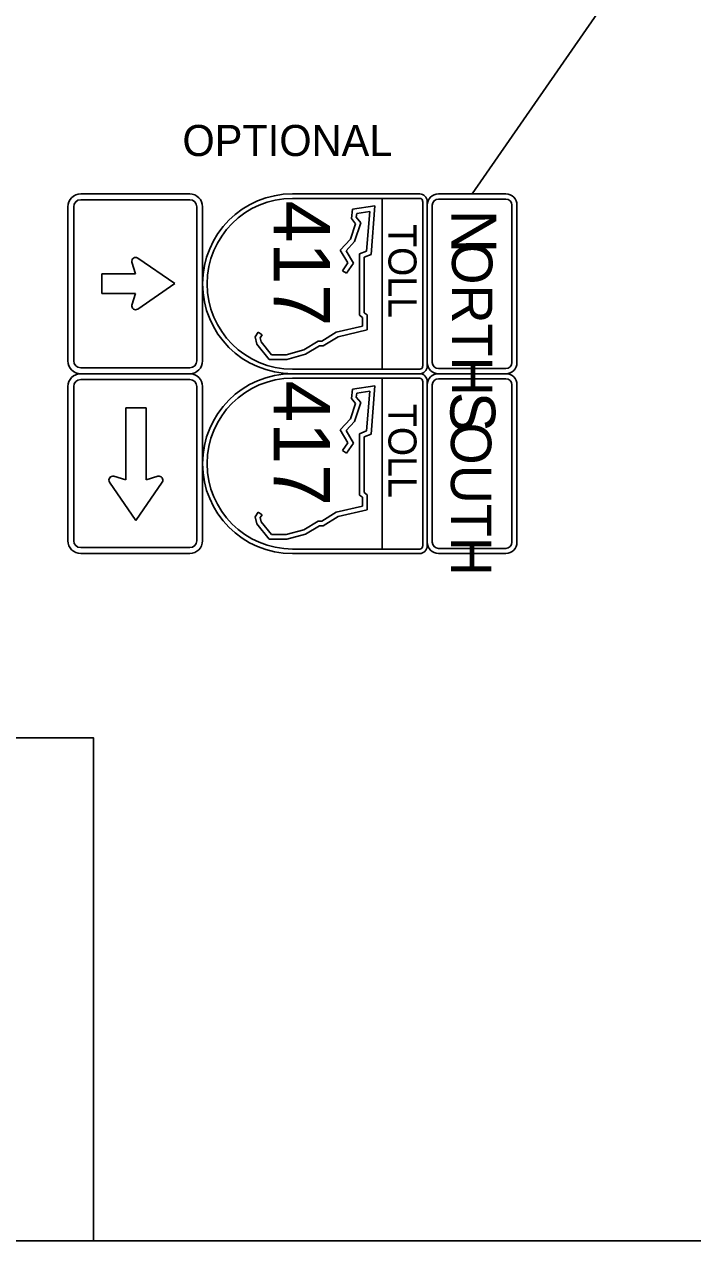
# Model space of a CAD drawing. Extents: x -830008.4 to -829992.7, y 1290284.1 to 1290294.4.
# Drawn here: x -830003.674 to -830002.168, y 1290285.328 to 1290288.067 of the extents above; entities that cross this region are included whole.
import ezdxf

# ---------------------------------------------------------------- set-up
doc = ezdxf.new("R2010")
doc.units = 0
for name, color, linetype in [('1', 7, 'Continuous'), ('SheetBorder_dp', 7, 'Continuous'), ('SheetLines_dp', 7, 'Continuous')]:
    doc.layers.add(name, color=color, linetype=linetype)

msp = doc.modelspace()

# ---------------------------------------------------------------- linework, layer by layer
at = {"layer": '1'}
msp.add_line((-830001.6762, 1290289.1116), (-830002.665, 1290287.6856), dxfattribs=at)
msp.add_lwpolyline([(-830007.4742, 1290285.328), (-830003.5187, 1290285.328), (-830003.5187, 1290286.4608), (-830007.4742, 1290286.4608)], close=True, dxfattribs=at)
at = {"layer": 'SheetBorder_dp'}
for p, q in [((-830002.9344, 1290287.6508), (-830002.8844, 1290287.6586)), ((-830002.8844, 1290287.6586), (-830002.8928, 1290287.5492)), ((-830002.937, 1290287.6298), (-830002.9344, 1290287.6508)), ((-830002.928, 1290287.6184), (-830002.937, 1290287.6298)), ((-830002.9249, 1290287.6416), (-830002.926, 1290287.6329)), ((-830002.926, 1290287.6329), (-830002.9162, 1290287.6205)), ((-830002.8959, 1290287.6461), (-830002.9249, 1290287.6416)), ((-830002.9028, 1290287.5566), (-830002.8959, 1290287.6461)), ((-830002.9393, 1290287.5838), (-830002.928, 1290287.6184)), ((-830002.9162, 1290287.6205), (-830002.93, 1290287.5783)), ((-830002.9622, 1290287.559), (-830002.9393, 1290287.5838)), ((-830002.93, 1290287.5783), (-830002.9491, 1290287.5576)), ((-830002.9451, 1290287.5299), (-830002.9622, 1290287.559)), ((-830002.9491, 1290287.5576), (-830002.9326, 1290287.5295)), ((-830002.9191, 1290287.5503), (-830002.9028, 1290287.5566)), ((-830002.9191, 1290287.4121), (-830002.9191, 1290287.5503)), ((-830002.8928, 1290287.5492), (-830002.9086, 1290287.5431)), ((-830003.4317, 1290287.5317), (-830003.4239, 1290287.5056)), ((-830003.335, 1290287.4835), (-830003.4188, 1290287.5411)), ((-830002.9568, 1290287.5126), (-830002.9451, 1290287.5299)), ((-830002.9326, 1290287.5295), (-830002.9481, 1290287.5067)), ((-830002.9086, 1290287.5431), (-830002.9086, 1290287.4177)), ((-830003.4239, 1290287.5056), (-830003.4995, 1290287.5056)), ((-830003.4995, 1290287.5056), (-830003.4995, 1290287.4613)), ((-830002.9481, 1290287.5067), (-830002.9568, 1290287.5126)), ((-830003.4188, 1290287.4259), (-830003.335, 1290287.4835)), ((-830003.4995, 1290287.4613), (-830003.4239, 1290287.4613)), ((-830003.4239, 1290287.4613), (-830003.4317, 1290287.4353)), ((-830002.9121, 1290287.4073), (-830002.9191, 1290287.4121)), ((-830002.9121, 1290287.3876), (-830002.9121, 1290287.4073)), ((-830002.9086, 1290287.4177), (-830002.9016, 1290287.4129)), ((-830002.9016, 1290287.4129), (-830002.9016, 1290287.3792)), ((-830002.9714, 1290287.3738), (-830002.9121, 1290287.3876)), ((-830003.1544, 1290287.3636), (-830003.1472, 1290287.374)), ((-830003.1505, 1290287.3472), (-830003.1544, 1290287.3636)), ((-830003.1472, 1290287.374), (-830003.1385, 1290287.368)), ((-830003.1385, 1290287.368), (-830003.143, 1290287.3615)), ((-830003.143, 1290287.3615), (-830003.1408, 1290287.352)), ((-830003.0444, 1290287.3341), (-830003.0121, 1290287.3536)), ((-830003.0121, 1290287.3536), (-830003.0038, 1290287.3536)), ((-830003.0038, 1290287.3536), (-830002.9714, 1290287.3738)), ((-830002.9673, 1290287.3639), (-830003.0007, 1290287.3431)), ((-830002.9016, 1290287.3792), (-830002.9673, 1290287.3639)), ((-830003.1222, 1290287.3127), (-830003.1505, 1290287.3472)), ((-830003.1408, 1290287.352), (-830003.1172, 1290287.3232)), ((-830003.084, 1290287.3232), (-830003.0444, 1290287.3341)), ((-830003.0092, 1290287.3431), (-830003.0402, 1290287.3243)), ((-830003.0007, 1290287.3431), (-830003.0092, 1290287.3431)), ((-830003.0826, 1290287.3127), (-830003.1222, 1290287.3127)), ((-830003.1172, 1290287.3232), (-830003.084, 1290287.3232)), ((-830003.0402, 1290287.3243), (-830003.0826, 1290287.3127)), ((-830002.937, 1290287.2248), (-830002.9344, 1290287.2458)), ((-830002.9344, 1290287.2458), (-830002.8844, 1290287.2536)), ((-830002.8844, 1290287.2536), (-830002.8928, 1290287.1442)), ((-830002.928, 1290287.2134), (-830002.937, 1290287.2248)), ((-830002.9162, 1290287.2155), (-830002.93, 1290287.1733)), ((-830002.9249, 1290287.2366), (-830002.926, 1290287.2279)), ((-830002.926, 1290287.2279), (-830002.9162, 1290287.2155)), ((-830002.8959, 1290287.2411), (-830002.9249, 1290287.2366)), ((-830002.9028, 1290287.1516), (-830002.8959, 1290287.2411)), ((-830003.4456, 1290287.0415), (-830003.4456, 1290287.2039)), ((-830003.4456, 1290287.2039), (-830003.4001, 1290287.2039)), ((-830003.4001, 1290287.2039), (-830003.4001, 1290287.0415)), ((-830002.9393, 1290287.1788), (-830002.928, 1290287.2134)), ((-830002.9622, 1290287.154), (-830002.9393, 1290287.1788)), ((-830002.93, 1290287.1733), (-830002.9491, 1290287.1526)), ((-830002.9451, 1290287.1249), (-830002.9622, 1290287.154)), ((-830002.9491, 1290287.1526), (-830002.9326, 1290287.1245)), ((-830002.9191, 1290287.1453), (-830002.9028, 1290287.1516)), ((-830002.9191, 1290287.0071), (-830002.9191, 1290287.1453)), ((-830002.8928, 1290287.1442), (-830002.9086, 1290287.1381)), ((-830002.9086, 1290287.1381), (-830002.9086, 1290287.0127)), ((-830002.9568, 1290287.1076), (-830002.9451, 1290287.1249)), ((-830002.9481, 1290287.1017), (-830002.9568, 1290287.1076)), ((-830002.9326, 1290287.1245), (-830002.9481, 1290287.1017)), ((-830003.4228, 1290286.95), (-830003.4821, 1290287.0362)), ((-830003.4724, 1290287.0495), (-830003.4456, 1290287.0415)), ((-830003.3636, 1290287.0362), (-830003.4228, 1290286.95)), ((-830003.4001, 1290287.0415), (-830003.3732, 1290287.0495)), ((-830002.9121, 1290287.0023), (-830002.9191, 1290287.0071)), ((-830002.9121, 1290286.9826), (-830002.9121, 1290287.0023)), ((-830002.9086, 1290287.0127), (-830002.9016, 1290287.0079)), ((-830002.9016, 1290287.0079), (-830002.9016, 1290286.9742)), ((-830003.1544, 1290286.9586), (-830003.1472, 1290286.969)), ((-830003.1472, 1290286.969), (-830003.1385, 1290286.963)), ((-830003.0038, 1290286.9486), (-830002.9714, 1290286.9688)), ((-830002.9714, 1290286.9688), (-830002.9121, 1290286.9826)), ((-830002.9016, 1290286.9742), (-830002.9673, 1290286.9589)), ((-830003.1505, 1290286.9422), (-830003.1544, 1290286.9586)), ((-830003.1222, 1290286.9077), (-830003.1505, 1290286.9422)), ((-830003.1385, 1290286.963), (-830003.143, 1290286.9565)), ((-830003.143, 1290286.9565), (-830003.1408, 1290286.947)), ((-830003.1408, 1290286.947), (-830003.1172, 1290286.9182)), ((-830003.0444, 1290286.9291), (-830003.0121, 1290286.9486)), ((-830003.0121, 1290286.9486), (-830003.0038, 1290286.9486)), ((-830002.9673, 1290286.9589), (-830003.0007, 1290286.9381)), ((-830003.1172, 1290286.9182), (-830003.084, 1290286.9182)), ((-830003.084, 1290286.9182), (-830003.0444, 1290286.9291)), ((-830003.0402, 1290286.9193), (-830003.0826, 1290286.9077)), ((-830003.0092, 1290286.9381), (-830003.0402, 1290286.9193)), ((-830003.0007, 1290286.9381), (-830003.0092, 1290286.9381)), ((-830003.0826, 1290286.9077), (-830003.1222, 1290286.9077))]:
    msp.add_line(p, q, dxfattribs=at)
for points in [[(-830003.5473, 1290287.6856), (-830003.3015, 1290287.6856)], [(-830003.07, 1290287.6856), (-830002.7832, 1290287.6856)], [(-830002.741, 1290287.6856), (-830002.5891, 1290287.6856)], [(-830003.5763, 1290287.3095), (-830003.5763, 1290287.6566)], [(-830003.563, 1290287.3095), (-830003.563, 1290287.6566)], [(-830003.5473, 1290287.6723), (-830003.3014, 1290287.6723)], [(-830003.2858, 1290287.6566), (-830003.2858, 1290287.3095)], [(-830003.2725, 1290287.6566), (-830003.2725, 1290287.3095)], [(-830003.07, 1290287.6754), (-830002.7832, 1290287.6754)], [(-830002.8675, 1290287.6754), (-830002.8675, 1290287.2907)], [(-830002.7764, 1290287.6687), (-830002.7764, 1290287.2974)], [(-830002.7663, 1290287.6687), (-830002.7663, 1290287.2974)], [(-830002.7663, 1290287.3059), (-830002.7663, 1290287.6603)], [(-830002.7547, 1290287.3059), (-830002.7547, 1290287.6603)], [(-830002.741, 1290287.674), (-830002.5891, 1290287.674)], [(-830002.5754, 1290287.6603), (-830002.5754, 1290287.3059)], [(-830002.5638, 1290287.6603), (-830002.5638, 1290287.3059)], [(-830003.3014, 1290287.2938), (-830003.5473, 1290287.2938)], [(-830003.3015, 1290287.2806), (-830003.5473, 1290287.2806)], [(-830003.3015, 1290287.2806), (-830003.5473, 1290287.2806)], [(-830002.7832, 1290287.2907), (-830003.07, 1290287.2907)], [(-830002.7832, 1290287.2806), (-830003.07, 1290287.2806)], [(-830003.07, 1290287.2806), (-830002.7832, 1290287.2806)], [(-830003.07, 1290287.2704), (-830002.7832, 1290287.2704)], [(-830002.8675, 1290287.2704), (-830002.8675, 1290286.8857)], [(-830002.5891, 1290287.2922), (-830002.741, 1290287.2922)], [(-830002.741, 1290287.2806), (-830002.5891, 1290287.2806)], [(-830002.5891, 1290287.2806), (-830002.741, 1290287.2806)], [(-830003.5763, 1290287.2516), (-830003.5763, 1290286.9045)], [(-830003.563, 1290287.2516), (-830003.563, 1290286.9045)], [(-830003.3014, 1290287.2673), (-830003.5473, 1290287.2673)], [(-830003.2858, 1290286.9045), (-830003.2858, 1290287.2516)], [(-830003.2725, 1290286.9045), (-830003.2725, 1290287.2516)], [(-830002.7764, 1290287.2637), (-830002.7764, 1290286.8924)], [(-830002.7663, 1290287.2637), (-830002.7663, 1290286.8924)], [(-830002.7663, 1290286.9009), (-830002.7663, 1290287.2553)], [(-830002.7547, 1290286.9009), (-830002.7547, 1290287.2553)], [(-830002.741, 1290287.269), (-830002.5891, 1290287.269)], [(-830002.5754, 1290287.2553), (-830002.5754, 1290286.9009)], [(-830002.5638, 1290287.2553), (-830002.5638, 1290286.9009)], [(-830003.5473, 1290286.8888), (-830003.3014, 1290286.8888)], [(-830002.5891, 1290286.8872), (-830002.741, 1290286.8872)], [(-830003.5473, 1290286.8756), (-830003.3015, 1290286.8756)], [(-830002.7832, 1290286.8857), (-830003.07, 1290286.8857)], [(-830002.7832, 1290286.8756), (-830003.07, 1290286.8756)], [(-830002.5891, 1290286.8756), (-830002.741, 1290286.8756)]]:
    msp.add_lwpolyline(points, dxfattribs=at)
for centre, radius, start, end in [((-830003.5473, 1290287.6566), 0.0289, 90, 180), ((-830003.3015, 1290287.6566), 0.0289, 360, 90), ((-830003.07, 1290287.4831), 0.2025, 90, 270), ((-830002.7832, 1290287.6687), 0.0169, 0, 90), ((-830002.741, 1290287.6603), 0.0253, 90, 180), ((-830002.5891, 1290287.6603), 0.0253, 0, 90), ((-830003.5473, 1290287.6566), 0.0157, 90, 180), ((-830003.3015, 1290287.6566), 0.0157, 0, 89.9456), ((-830003.07, 1290287.4831), 0.1924, 90, 270), ((-830002.7832, 1290287.6687), 0.00675, 0, 90), ((-830002.741, 1290287.6603), 0.0137, 90, 180), ((-830002.5891, 1290287.6603), 0.0137, 0, 90), ((-830003.4236, 1290287.5341), 0.00844, 55.5119, 196.6443), ((-830003.4236, 1290287.4329), 0.00844, 163.3557, 304.4881), ((-830003.5473, 1290287.3095), 0.0289, 180, 270), ((-830003.5473, 1290287.3095), 0.0157, 180, 270), ((-830003.3015, 1290287.3095), 0.0289, 270, 0), ((-830003.3015, 1290287.3095), 0.0157, 270.0544, 0), ((-830002.7832, 1290287.2974), 0.0169, 270, 0), ((-830002.7832, 1290287.2974), 0.00675, 270, 0), ((-830002.741, 1290287.3059), 0.0253, 180, 270), ((-830002.741, 1290287.3059), 0.0137, 180, 270), ((-830002.5891, 1290287.3059), 0.0253, 270, 0), ((-830002.5891, 1290287.3059), 0.0137, 270, 0), ((-830003.5473, 1290287.2516), 0.0289, 90, 180), ((-830003.3015, 1290287.2516), 0.0289, 0, 90), ((-830003.07, 1290287.0781), 0.2025, 90, 270), ((-830003.07, 1290287.0781), 0.1924, 90, 270), ((-830002.7832, 1290287.2637), 0.0169, 0, 90), ((-830002.7832, 1290287.2637), 0.00675, 0, 90), ((-830002.741, 1290287.2553), 0.0253, 90, 180), ((-830002.5891, 1290287.2553), 0.0253, 360, 90), ((-830003.5473, 1290287.2516), 0.0157, 90, 180), ((-830003.3015, 1290287.2516), 0.0157, 0, 89.9456), ((-830002.741, 1290287.2553), 0.0137, 90, 180), ((-830002.5891, 1290287.2553), 0.0137, 360, 90), ((-830003.4749, 1290287.0412), 0.00868, 73.3557, 214.4881), ((-830003.3708, 1290287.0412), 0.00868, 325.5119, 106.6443), ((-830003.5473, 1290286.9045), 0.0289, 180, 270), ((-830003.5473, 1290286.9045), 0.0157, 180, 270), ((-830003.3015, 1290286.9045), 0.0289, 270, 0), ((-830003.3015, 1290286.9045), 0.0157, 270.0544, 0), ((-830002.7832, 1290286.8924), 0.0169, 270, 0), ((-830002.7832, 1290286.8924), 0.00675, 270, 0), ((-830002.741, 1290286.9009), 0.0253, 180, 270), ((-830002.741, 1290286.9009), 0.0137, 180, 270), ((-830002.5891, 1290286.9009), 0.0253, 270, 360), ((-830002.5891, 1290286.9009), 0.0137, 270, 360)]:
    msp.add_arc(centre, radius, start, end, dxfattribs=at)
at = {"layer": 'SheetLines_dp'}
msp.add_lwpolyline([(-830007.4742, 1290294.228), (-829992.7742, 1290294.228), (-829992.7742, 1290285.328), (-830007.4742, 1290285.328)], close=True, dxfattribs=at)

# ---------------------------------------------------------------- texts
at = {"layer": '1'}
msp.add_text('OPTIONAL ', height=0.07, rotation=0.0044, dxfattribs=at).set_placement((-830003.318, 1290287.7708))
at = {"layer": 'SheetBorder_dp'}
for s, height, p in [('417', 0.12656, (-830003.1122, 1290287.6704)), ('N', 0.1013, (-830002.7116, 1290287.65)), ('TOLL', 0.06328, (-830002.8536, 1290287.6175)), ('ORTH', 0.09113, (-830002.7104, 1290287.5762)), ('417', 0.12656, (-830003.1122, 1290287.2654)), ('S', 0.1013, (-830002.714, 1290287.2397)), ('TOLL', 0.06328, (-830002.8536, 1290287.2125)), ('OUTH', 0.09113, (-830002.7128, 1290287.1705))]:
    msp.add_text(s, height=height, rotation=270, dxfattribs=at).set_placement(p)

doc.saveas('drawing.dxf')
